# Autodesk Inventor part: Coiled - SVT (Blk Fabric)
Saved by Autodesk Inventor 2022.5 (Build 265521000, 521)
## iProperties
Created: 2025-02
Part Number: Coiled - SVT (Blk Fabric)
Material: Generic
Document SubType Name: Modeling
Designer: AdminForWorker
Density: 1 g/cm^3
Appearance: Default
Title: Coiled - SVT (Blk Fabric)
Author: AdminForWorker
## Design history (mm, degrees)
feature "Coiled - SVT (Blk Fabric)"
body "Solid1"
